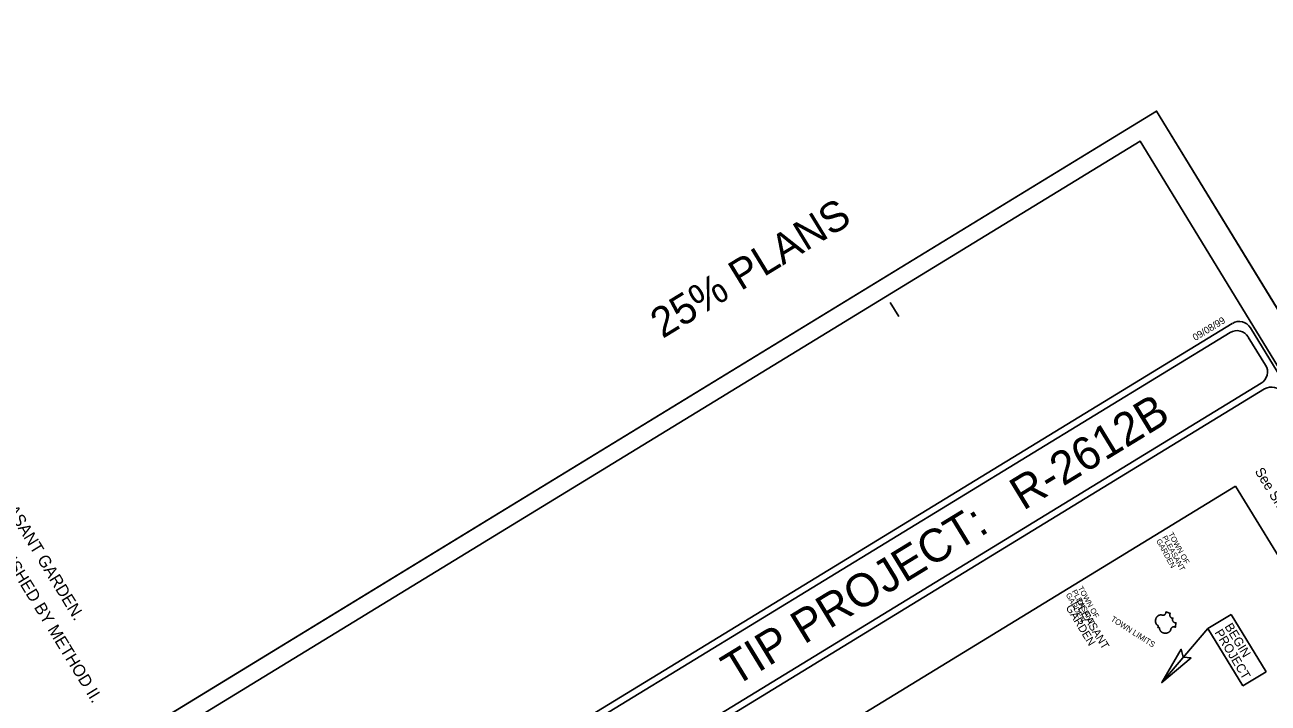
# Model space of a CAD drawing. Extents: x 1750583 to 1791140, y 783580 to 827376.
# Drawn here: x 1772080 to 1782418, y 821536 to 827177 of the extents above; entities that cross this region are included whole.
import ezdxf

# ---------------------------------------------------------------- set-up
doc = ezdxf.new("R2010")
doc.units = 0
for name, color, linetype in [('Default', 7, 'Continuous'), ('Prop Dimension Text', 7, 'Continuous'), ('Prop Horizontal Alignment', 7, 'Continuous'), ('Prop Terminator CELL', 7, 'Continuous'), ('Sheet Cutting Line CELL', 7, 'Continuous'), ('Sheet Plot Border Inside CELL', 7, 'Continuous'), ('Sheet Plot Border Outside CELL', 7, 'Continuous'), ('Sheet Title CELL', 7, 'Continuous')]:
    doc.layers.add(name, color=color, linetype=linetype)

msp = doc.modelspace()

# ---------------------------------------------------------------- linework, layer by layer
at = {"layer": 'Prop Dimension Text'}
msp.add_lwpolyline([(1781605, 822282), (1781604, 822281), (1781603, 822280), (1781603, 822279), (1781602, 822278), (1781601, 822276), (1781600, 822274), (1781600, 822271), (1781600, 822270), (1781600, 822267), (1781600, 822265), (1781601, 822262), (1781602, 822259), (1781603, 822257), (1781605, 822254), (1781607, 822252), (1781609, 822249), (1781610, 822248), (1781612, 822247), (1781613, 822245), (1781615, 822244), (1781617, 822244), (1781618, 822243), (1781620, 822242), (1781622, 822242), (1781623, 822242), (1781624, 822242), (1781626, 822243), (1781627, 822243), (1781628, 822244), (1781627, 822243), (1781627, 822242), (1781626, 822242), (1781625, 822241), (1781625, 822240), (1781624, 822238), (1781623, 822236), (1781623, 822235), (1781623, 822234), (1781623, 822232), (1781623, 822229), (1781623, 822228), (1781623, 822226), (1781624, 822225), (1781624, 822223), (1781625, 822222), (1781626, 822220), (1781626, 822219), (1781627, 822217), (1781628, 822216), (1781629, 822215), (1781630, 822213), (1781631, 822212), (1781632, 822211), (1781633, 822210), (1781635, 822209), (1781636, 822208), (1781638, 822207), (1781640, 822206), (1781641, 822205), (1781643, 822205), (1781645, 822204), (1781646, 822204), (1781647, 822205), (1781649, 822205), (1781650, 822205), (1781651, 822206), (1781652, 822206), (1781647, 822167), (1781646, 822167), (1781644, 822168), (1781643, 822169), (1781641, 822170), (1781640, 822170), (1781638, 822171), (1781637, 822171), (1781636, 822171), (1781634, 822171), (1781633, 822171), (1781631, 822171), (1781630, 822171), (1781627, 822171), (1781626, 822170), (1781625, 822170), (1781622, 822169), (1781621, 822168), (1781620, 822167), (1781619, 822166), (1781618, 822166), (1781617, 822165), (1781616, 822164), (1781615, 822163), (1781613, 822161), (1781612, 822160), (1781611, 822157), (1781609, 822154), (1781609, 822153), (1781608, 822151), (1781608, 822148), (1781608, 822147), (1781607, 822145), (1781606, 822142), (1781606, 822141), (1781605, 822140), (1781605, 822139), (1781604, 822137), (1781603, 822136), (1781601, 822134), (1781600, 822132), (1781599, 822131), (1781596, 822129), (1781595, 822128), (1781593, 822126), (1781590, 822124), (1781587, 822123), (1781583, 822121), (1781581, 822120), (1781578, 822120), (1781575, 822119), (1781572, 822118), (1781569, 822118), (1781565, 822118), (1781563, 822118), (1781561, 822118), (1781558, 822118), (1781555, 822119), (1781552, 822119), (1781549, 822120), (1781546, 822121), (1781544, 822122), (1781542, 822122), (1781539, 822124), (1781536, 822125), (1781534, 822127), (1781532, 822128), (1781530, 822130), (1781526, 822133), (1781525, 822135), (1781524, 822136), (1781523, 822138), (1781522, 822139), (1781520, 822141), (1781519, 822143), (1781518, 822145), (1781517, 822148), (1781517, 822150), (1781516, 822152), (1781516, 822155), (1781516, 822159), (1781516, 822161), (1781516, 822161), (1781515, 822163), (1781514, 822164), (1781513, 822165), (1781512, 822165), (1781511, 822166), (1781510, 822166), (1781509, 822166), (1781507, 822167), (1781507, 822167), (1781505, 822167), (1781504, 822167), (1781503, 822166), (1781501, 822166), (1781502, 822167), (1781503, 822169), (1781504, 822170), (1781504, 822171), (1781505, 822172), (1781505, 822174), (1781505, 822175), (1781505, 822177), (1781505, 822178), (1781505, 822179), (1781505, 822180), (1781504, 822181), (1781504, 822181), (1781503, 822182), (1781502, 822183), (1781500, 822183), (1781499, 822184), (1781497, 822185), (1781496, 822186), (1781494, 822187), (1781493, 822188), (1781492, 822189), (1781490, 822191), (1781489, 822192), (1781488, 822194), (1781487, 822195), (1781486, 822197), (1781486, 822198), (1781485, 822200), (1781484, 822202), (1781483, 822204), (1781483, 822206), (1781482, 822208), (1781482, 822210), (1781481, 822213), (1781481, 822216), (1781481, 822219), (1781481, 822223), (1781482, 822227), (1781482, 822230), (1781483, 822234), (1781484, 822236), (1781485, 822240), (1781487, 822243), (1781488, 822245), (1781489, 822248), (1781491, 822250), (1781492, 822252), (1781494, 822254), (1781496, 822256), (1781497, 822257), (1781499, 822259), (1781500, 822261), (1781502, 822262), (1781504, 822264), (1781506, 822265), (1781508, 822266), (1781510, 822267), (1781513, 822268), (1781515, 822269), (1781517, 822269), (1781519, 822270), (1781521, 822270), (1781523, 822270), (1781525, 822270), (1781527, 822270), (1781529, 822270), (1781532, 822270), (1781534, 822269), (1781536, 822268), (1781538, 822268), (1781539, 822268), (1781541, 822267), (1781543, 822267), (1781544, 822267), (1781546, 822268), (1781548, 822268), (1781550, 822268), (1781551, 822269), (1781553, 822269), (1781555, 822270), (1781557, 822271), (1781558, 822272), (1781560, 822273), (1781562, 822275), (1781563, 822276), (1781564, 822278), (1781565, 822279), (1781566, 822281), (1781567, 822284), (1781568, 822285), (1781568, 822287), (1781568, 822289), (1781568, 822291), (1781568, 822292), (1781568, 822294), (1781568, 822295)], close=True, dxfattribs=at)
at = {"layer": 'Prop Horizontal Alignment'}
for p, q in [((1781917, 822157), (1782110, 822274)), ((1782110, 822274), (1782401, 821798)), ((1781533, 821708), (1781917, 822157)), ((1782208, 821680), (1781917, 822157)), ((1782401, 821798), (1782208, 821680))]:
    msp.add_line(p, q, dxfattribs=at)
at = {"layer": 'Prop Terminator CELL'}
msp.add_lwpolyline([(1781779, 821912), (1781533, 821708), (1781696, 821985), (1781712, 821918)], close=True, dxfattribs=at)
at = {"layer": 'Sheet Cutting Line CELL'}
for q in [(1771176, 820157), (1791140, 810668)]:
    msp.add_line((1781491, 826460), q, dxfattribs=at)
at = {"layer": 'Sheet Plot Border Inside CELL'}
msp.add_lwpolyline([(1771461, 820164), (1781009, 804537), (1790904, 810582), (1781355, 826209)], close=True, dxfattribs=at)
at = {"layer": 'Sheet Plot Border Outside CELL'}
msp.add_lwpolyline([(1791140, 810668), (1781491, 826460), (1771176, 820157), (1780825, 804366)], close=True, dxfattribs=at)
at = {"layer": 'Sheet Title CELL'}
for p, q in [((1779276, 824868), (1779348, 824751)), ((1779276, 824868), (1779348, 824751)), ((1772795, 818352), (1782360, 824196)), ((1774558, 819365), (1782388, 824149)), ((1778878, 821342), (1782148, 823340)), ((1782148, 823340), (1783700, 820799))]:
    msp.add_line(p, q, dxfattribs=at)
for points in [[(1782120, 824693), (1772461, 818792)], [(1782120, 824693), (1772461, 818792)], [(1790751, 810778), (1782271, 824657)], [(1782102, 824618), (1772537, 818774)], [(1782396, 824347), (1782253, 824581)]]:
    msp.add_lwpolyline(points, dxfattribs=at)
for centre, start, end in [((1782178, 824600), 31.4249, 121.4249), ((1782159, 824524), 31.4249, 121.4249), ((1782303, 824290), 301.4249, 31.4249), ((1782446, 824055), 31.4249, 121.4249)]:
    msp.add_arc(centre, 110, start, end, dxfattribs=at)

# ---------------------------------------------------------------- texts
at = {"layer": 'Default'}
for s, p in [('GARDEN', (1781485, 822887)), ('PLEASANT', (1781535, 822915)), ('TOWN OF', (1781586, 822943)), ('PLEASANT', (1780784, 822466)), ('TOWN OF', (1780835, 822494)), ('GARDEN', (1780734, 822438))]:
    msp.add_text(s, height=45, rotation=298.8327, dxfattribs=at).set_placement(p)
at = {"layer": 'Prop Dimension Text'}
for s, height, rotation, p in [('THIS PROJECT IS WITHIN THE MUNICIPAL LIMITS OF THE TOWN OF PLEASANT GARDEN.', 100, 301.4249, (1769494, 827127)), ('CLEARING ON THIS PROJECT SHALL BE PERFORMED TO THE LIMITS ESTABLISHED BY METHOD II.', 100, 301.4249, (1769294, 827013)), ('PLEASANT', 66.6, 301.4249, (1780802, 822374)), ('GARDEN', 66.6, 301.4249, (1780732, 822331)), ('TOWN LIMITS', 47.92, 327.328, (1781105, 822224))]:
    msp.add_text(s, height=height, rotation=rotation, dxfattribs=at).set_placement(p)
at = {"layer": 'Prop Horizontal Alignment'}
for s, p in [('BEGIN', (1782053, 822174)), ('PROJECT', (1781970, 822124))]:
    msp.add_text(s, height=74.7, rotation=301.2478, dxfattribs=at).set_placement(p)
at = {"layer": 'Sheet Title CELL'}
for s, height, rotation, p in [('25% PLANS', 250, 31.4249, (1777383, 824564)), ('09/08/99', 57.7, 31.4249, (1781812, 824547)), ('R-2612B', 274.7, 31.4249, (1780382, 823134)), ('See Sheets 1-C Through 1-E For Survey Control Sheets', 82.5, 301.4249, (1782304, 823465)), ('TIP PROJECT:', 274.73, 31.4249, (1777985, 821670))]:
    msp.add_text(s, height=height, rotation=rotation, dxfattribs=at).set_placement(p)

doc.saveas('drawing.dxf')
